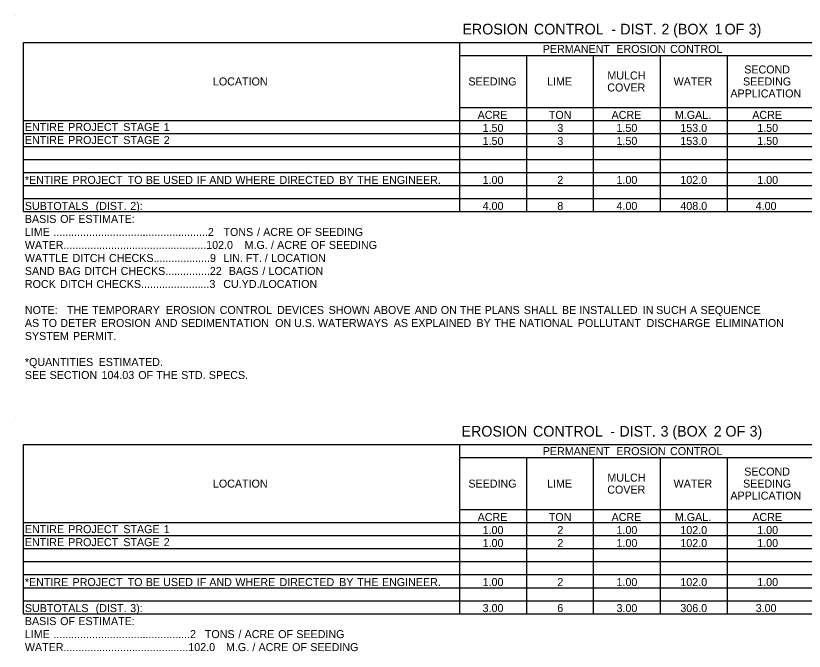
# Model space of a CAD drawing. Extents: x 544250 to 1930787, y -1948365 to 596640.
# Drawn here: x 555883 to 556474, y -1947815 to -1947339 of the extents above; entities that cross this region are included whole.
import ezdxf

# ---------------------------------------------------------------- set-up
doc = ezdxf.new("R2010")
doc.units = 0
doc.layers.add('Default', color=7, linetype='Continuous')

msp = doc.modelspace()

# ---------------------------------------------------------------- linework, layer by layer
at = {"layer": 'Default'}
for p, q in [((555882.8, -1947338.62), (555882.8, -1947338.62)), ((555888.65, -1947358.61), (556771.02, -1947358.61)), ((555888.65, -1947485.36), (555888.65, -1947358.61)), ((555888.65, -1947485.36), (555888.65, -1947358.61)), ((556215.76, -1947485.36), (556215.76, -1947358.61)), ((556215.76, -1947368.36), (556771.02, -1947368.36)), ((556265.97, -1947485.36), (556265.97, -1947368.36)), ((556316.18, -1947485.36), (556316.18, -1947368.36)), ((556366.4, -1947485.36), (556366.4, -1947368.36)), ((556416.61, -1947485.36), (556416.61, -1947368.36)), ((556215.76, -1947407.36), (556771.02, -1947407.36)), ((556265.97, -1947485.36), (556265.97, -1947407.36)), ((556316.18, -1947475.61), (556316.18, -1947407.36)), ((556366.4, -1947475.61), (556366.4, -1947407.36)), ((556416.61, -1947475.61), (556416.61, -1947407.36)), ((555888.65, -1947417.11), (556771.02, -1947417.11)), ((555888.65, -1947426.86), (556771.02, -1947426.86)), ((555888.65, -1947436.61), (556771.02, -1947436.61)), ((555888.65, -1947446.36), (556771.02, -1947446.36)), ((555888.65, -1947456.11), (556771.02, -1947456.11)), ((555888.65, -1947465.86), (556771.02, -1947465.86)), ((555888.65, -1947475.61), (556771.02, -1947475.61)), ((556215.76, -1947485.36), (556215.76, -1947475.61)), ((556265.97, -1947475.61), (556477.06, -1947475.61)), ((555888.65, -1947485.36), (556771.02, -1947485.36)), ((555882.8, -1947640.06), (555882.8, -1947640.06)), ((555888.65, -1947660.05), (556771.02, -1947660.05)), ((555888.65, -1947786.8), (555888.65, -1947660.05)), ((555888.65, -1947786.8), (555888.65, -1947660.05)), ((556215.76, -1947786.8), (556215.76, -1947660.05)), ((556215.76, -1947669.8), (556771.02, -1947669.8)), ((556265.97, -1947786.8), (556265.97, -1947669.8)), ((556316.18, -1947786.8), (556316.18, -1947669.8)), ((556366.4, -1947786.8), (556366.4, -1947669.8)), ((556416.61, -1947786.8), (556416.61, -1947669.8)), ((556215.76, -1947708.8), (556771.02, -1947708.8)), ((556265.97, -1947786.8), (556265.97, -1947708.8)), ((556316.18, -1947777.05), (556316.18, -1947708.8)), ((556366.4, -1947777.05), (556366.4, -1947708.8)), ((556416.61, -1947777.05), (556416.61, -1947708.8)), ((555888.65, -1947718.55), (556771.02, -1947718.55)), ((555888.65, -1947728.3), (556771.02, -1947728.3)), ((555888.65, -1947738.05), (556771.02, -1947738.05)), ((555888.65, -1947747.8), (556771.02, -1947747.8)), ((555888.65, -1947757.55), (556771.02, -1947757.55)), ((555888.65, -1947767.3), (556771.02, -1947767.3)), ((555888.65, -1947777.05), (556771.02, -1947777.05)), ((556215.76, -1947786.8), (556215.76, -1947777.05)), ((556265.97, -1947777.05), (556477.06, -1947777.05)), ((555888.65, -1947786.8), (556771.02, -1947786.8))]:
    msp.add_line(p, q, dxfattribs=at)

# ---------------------------------------------------------------- texts
for s, height, p in [('EROSION', 8, (556217.73, -1947352.62)), (' CONTROL', 8, (556268.39, -1947352.62)), (' DIST.', 8, (556333.17, -1947352.62)), (' 2', 8, (556364.07, -1947352.62)), (' (BOX', 8, (556372.83, -1947352.62)), (' 1', 8, (556403.86, -1947352.62)), (' OF', 8, (556411.37, -1947352.62)), (' 3)', 8, (556429.48, -1947352.62)), (' -', 8, (556326.43, -1947352.62)), ('PERMANENT', 6, (556278.02, -1947366.49)), (' EROSION', 6, (556330.95, -1947366.49)), (' CONTROL', 6, (556371.27, -1947366.49)), ('SECOND', 6, (556429.11, -1947381.86)), ('MULCH', 6, (556326.48, -1947386.36)), ('LOCATION', 6, (556030.65, -1947390.86)), ('SEEDING', 6, (556222.25, -1947390.86)), ('LIME', 6, (556281.27, -1947390.86)), ('WATER', 6, (556376.16, -1947390.86)), ('SEEDING', 6, (556428.22, -1947390.86)), ('COVER', 6, (556326.4, -1947395.36)), ('APPLICATION', 6, (556418.76, -1947399.86)), ('ACRE', 6, (556229.19, -1947415.91)), ('TON', 6, (556282.56, -1947415.91)), ('ACRE', 6, (556329.62, -1947415.91)), ('M.GAL.', 6, (556377.12, -1947415.91)), ('ACRE', 6, (556435.16, -1947415.91)), ('ENTIRE', 6, (555889.62, -1947424.99)), (' PROJECT', 6, (555919.92, -1947424.99)), (' STAGE', 6, (555961.21, -1947424.99)), (' 1', 6, (555991.51, -1947424.99)), ('1.50', 6, (556232.91, -1947425.66)), ('3', 6, (556288.94, -1947425.66)), ('1.50', 6, (556333.34, -1947425.66)), ('153.0', 6, (556381.22, -1947425.66)), ('1.50', 6, (556438.88, -1947425.66)), ('ENTIRE', 6, (555889.62, -1947434.74)), (' PROJECT', 6, (555919.92, -1947434.74)), (' STAGE', 6, (555961.21, -1947434.74)), (' 2', 6, (555991.51, -1947434.74)), ('1.50', 6, (556232.91, -1947435.41)), ('3', 6, (556288.94, -1947435.41)), ('1.50', 6, (556333.34, -1947435.41)), ('153.0', 6, (556381.22, -1947435.41)), ('1.50', 6, (556438.88, -1947435.41)), ('*ENTIRE', 6, (555889.62, -1947464.66)), (' PROJECT', 6, (555923.18, -1947464.66)), (' TO', 6, (555964.47, -1947464.66)), (' BE', 6, (555978.07, -1947464.66)), (' USED', 6, (555991.13, -1947464.66)), (' IF', 6, (556016.31, -1947464.66)), (' AND', 6, (556025.7, -1947464.66)), (' WHERE', 6, (556045.28, -1947464.66)), (' DIRECTED', 6, (556078.37, -1947464.66)), (' BY', 6, (556123.1, -1947464.66)), (' THE', 6, (556136.55, -1947464.66)), (' ENGINEER.', 6, (556155.2, -1947464.66)), ('1.00', 6, (556232.91, -1947464.66)), ('2', 6, (556288.97, -1947464.66)), ('1.00', 6, (556333.34, -1947464.66)), ('102.0', 6, (556381.22, -1947464.66)), ('1.00', 6, (556438.88, -1947464.66)), ('SUBTOTALS', 6, (555889.62, -1947484.16)), (' (DIST.', 6, (555940.45, -1947484.16)), (' 2):', 6, (555966.41, -1947484.16)), ('4.00', 6, (556232.92, -1947484.16)), ('8', 6, (556288.94, -1947484.16)), ('4.00', 6, (556333.34, -1947484.16)), ('408.0', 6, (556381.22, -1947484.16)), ('4.00', 6, (556437.72, -1947484.16)), ('BASIS', 6, (555889.62, -1947493.91)), (' OF', 6, (555913.88, -1947493.91)), (' ESTIMATE:', 6, (555927.47, -1947493.91)), ('LIME', 6, (555889.62, -1947503.66)), (' ....................................................2', 6, (555908.74, -1947503.66)), (' TONS', 6, (556036.32, -1947503.66)), (' /', 6, (556061.5, -1947503.66)), (' ACRE', 6, (556066.16, -1947503.66)), (' OF', 6, (556091.34, -1947503.66)), (' SEEDING', 6, (556104.93, -1947503.66)), ('WATER................................................102.0', 6, (555889.62, -1947513.41)), (' M.G.', 6, (556052.19, -1947513.41)), (' /', 6, (556071.95, -1947513.41)), (' ACRE', 6, (556076.61, -1947513.41)), (' OF', 6, (556101.78, -1947513.41)), (' SEEDING', 6, (556115.37, -1947513.41)), ('WATTLE', 6, (555889.62, -1947523.16)), (' DITCH', 6, (555923.17, -1947523.16)), (' CHECKS...................9', 6, (555950.44, -1947523.16)), (' LIN.', 6, (556036.23, -1947523.16)), (' FT.', 6, (556053.19, -1947523.16)), (' /', 6, (556067.36, -1947523.16)), (' LOCATION', 6, (556072.02, -1947523.16)), ('SAND', 6, (555889.62, -1947532.91)), (' BAG', 6, (555912.47, -1947532.91)), (' DITCH', 6, (555931.98, -1947532.91)), (' CHECKS...............22', 6, (555959.24, -1947532.91)), (' BAGS', 6, (556040.31, -1947532.91)), (' /', 6, (556065.5, -1947532.91)), (' LOCATION', 6, (556070.16, -1947532.91)), (' CU.YD./LOCATION', 6, (556036.18, -1947542.66)), ('ROCK', 6, (555889.62, -1947542.66)), (' DITCH', 6, (555913.83, -1947542.66)), (' CHECKS.......................3', 6, (555941.09, -1947542.66)), ('NOTE:', 6, (555889.62, -1947562.16)), ('   THE', 6, (555914.51, -1947562.16)), (' TEMPORARY', 6, (555937.81, -1947562.16)), (' EROSION', 6, (555993.19, -1947562.16)), (' CONTROL', 6, (556033.49, -1947562.16)), (' DEVICES', 6, (556076.51, -1947562.16)), (' SHOWN', 6, (556115.21, -1947562.16)), (' ABOVE', 6, (556148.99, -1947562.16)), (' AND', 6, (556179.76, -1947562.16)), (' ON', 6, (556199.34, -1947562.16)), (' THE', 6, (556213.56, -1947562.16)), (' PLANS', 6, (556232.21, -1947562.16)), (' SHALL', 6, (556261.59, -1947562.16)), (' BE', 6, (556290.19, -1947562.16)), (' INSTALLED', 6, (556303.25, -1947562.16)), (' IN', 6, (556350.79, -1947562.16)), (' SUCH', 6, (556360.81, -1947562.16)), (' A', 6, (556386.22, -1947562.16)), (' SEQUENCE', 6, (556394.16, -1947562.16)), ('AS', 6, (555889.62, -1947571.91)), (' TO', 6, (555900.37, -1947571.91)), (' EROSION', 6, (555944.6, -1947571.91)), (' SEDIMENTATION', 6, (556004.49, -1947571.91)), (' ON', 6, (556075.07, -1947571.91)), (' U.S.', 6, (556089.29, -1947571.91)), (' WATERWAYS', 6, (556107.19, -1947571.91)), (' AS', 6, (556164.04, -1947571.91)), (' NATIONAL', 6, (556258.16, -1947571.91)), (' POLLUTANT', 6, (556302.11, -1947571.91)), (' DISCHARGE', 6, (556353.65, -1947571.91)), (' ELIMINATION', 6, (556405.38, -1947571.91)), (' DETER', 6, (555913.96, -1947571.91)), (' AND', 6, (555984.9, -1947571.91)), (' EXPLAINED', 6, (556177.11, -1947571.91)), (' BY', 6, (556226.06, -1947571.91)), (' THE', 6, (556239.51, -1947571.91)), ('SYSTEM', 6, (555889.62, -1947581.66)), (' PERMIT.', 6, (555923.47, -1947581.66)), ('*QUANTITIES', 6, (555889.62, -1947601.16)), (' ESTIMATED.', 6, (555942.75, -1947601.16)), ('SEE', 6, (555889.62, -1947610.91)), (' SECTION', 6, (555905.95, -1947610.91)), (' 104.03', 6, (555944.86, -1947610.91)), (' OF', 6, (555972.44, -1947610.91)), (' THE', 6, (555986.02, -1947610.91)), (' STD.', 6, (556004.67, -1947610.91)), (' SPECS.', 6, (556025.37, -1947610.91)), ('EROSION', 8, (556217.07, -1947654.06)), (' CONTROL', 8, (556267.72, -1947654.06)), (' DIST.', 8, (556332.5, -1947654.06)), (' 3', 8, (556363.41, -1947654.06)), (' (BOX', 8, (556372.24, -1947654.06)), (' 2', 8, (556403.28, -1947654.06)), (' OF', 8, (556412.04, -1947654.06)), (' 3)', 8, (556430.15, -1947654.06)), (' -', 8, (556325.76, -1947654.06)), ('PERMANENT', 6, (556278.02, -1947667.93)), (' EROSION', 6, (556330.95, -1947667.93)), (' CONTROL', 6, (556371.27, -1947667.93)), ('SECOND', 6, (556429.11, -1947683.3)), ('MULCH', 6, (556326.48, -1947687.8)), ('LOCATION', 6, (556030.65, -1947692.3)), ('SEEDING', 6, (556222.25, -1947692.3)), ('LIME', 6, (556281.27, -1947692.3)), ('WATER', 6, (556376.16, -1947692.3)), ('SEEDING', 6, (556428.22, -1947692.3)), ('COVER', 6, (556326.4, -1947696.8)), ('APPLICATION', 6, (556418.76, -1947701.3)), ('ACRE', 6, (556229.19, -1947717.35)), ('TON', 6, (556282.56, -1947717.35)), ('ACRE', 6, (556329.62, -1947717.35)), ('M.GAL.', 6, (556377.12, -1947717.35)), ('ACRE', 6, (556435.16, -1947717.35)), ('ENTIRE', 6, (555889.62, -1947726.43)), (' PROJECT', 6, (555919.92, -1947726.43)), (' STAGE', 6, (555961.21, -1947726.43)), (' 1', 6, (555991.51, -1947726.43)), ('1.00', 6, (556232.91, -1947727.1)), ('2', 6, (556288.97, -1947727.1)), ('1.00', 6, (556333.34, -1947727.1)), ('102.0', 6, (556381.22, -1947727.1)), ('1.00', 6, (556438.88, -1947727.1)), ('ENTIRE', 6, (555889.62, -1947736.18)), (' PROJECT', 6, (555919.92, -1947736.18)), (' STAGE', 6, (555961.21, -1947736.18)), (' 2', 6, (555991.51, -1947736.18)), ('1.00', 6, (556232.91, -1947736.85)), ('2', 6, (556288.97, -1947736.85)), ('1.00', 6, (556333.34, -1947736.85)), ('102.0', 6, (556381.22, -1947736.85)), ('1.00', 6, (556438.88, -1947736.85)), ('*ENTIRE', 6, (555889.62, -1947766.1)), (' PROJECT', 6, (555923.18, -1947766.1)), (' TO', 6, (555964.47, -1947766.1)), (' BE', 6, (555978.07, -1947766.1)), (' USED', 6, (555991.13, -1947766.1)), (' IF', 6, (556016.31, -1947766.1)), (' AND', 6, (556025.7, -1947766.1)), (' WHERE', 6, (556045.28, -1947766.1)), (' DIRECTED', 6, (556078.37, -1947766.1)), (' BY', 6, (556123.1, -1947766.1)), (' THE', 6, (556136.55, -1947766.1)), (' ENGINEER.', 6, (556155.2, -1947766.1)), ('1.00', 6, (556232.91, -1947766.1)), ('2', 6, (556288.97, -1947766.1)), ('1.00', 6, (556333.34, -1947766.1)), ('102.0', 6, (556381.22, -1947766.1)), ('1.00', 6, (556438.88, -1947766.1)), ('SUBTOTALS', 6, (555889.62, -1947785.6)), (' (DIST.', 6, (555940.45, -1947785.6)), (' 3):', 6, (555966.41, -1947785.6)), ('3.00', 6, (556232.92, -1947785.6)), ('6', 6, (556288.9, -1947785.6)), ('3.00', 6, (556333.34, -1947785.6)), ('306.0', 6, (556381.22, -1947785.6)), ('3.00', 6, (556437.72, -1947785.6)), ('BASIS', 6, (555889.62, -1947795.35)), (' OF', 6, (555913.88, -1947795.35)), (' ESTIMATE:', 6, (555927.47, -1947795.35)), ('LIME', 6, (555889.62, -1947805.1)), (' ..............................................2', 6, (555908.74, -1947805.1)), (' TONS', 6, (556022.36, -1947805.1)), (' /', 6, (556047.54, -1947805.1)), (' ACRE', 6, (556052.2, -1947805.1)), (' OF', 6, (556077.37, -1947805.1)), (' SEEDING', 6, (556090.96, -1947805.1)), ('WATER..........................................102.0', 6, (555889.62, -1947814.85)), (' M.G.', 6, (556038.23, -1947814.85)), (' /', 6, (556057.98, -1947814.85)), (' ACRE', 6, (556062.64, -1947814.85)), (' OF', 6, (556087.82, -1947814.85)), (' SEEDING', 6, (556101.41, -1947814.85))]:
    msp.add_text(s, height=height, dxfattribs=at).set_placement(p)

doc.saveas('drawing.dxf')
